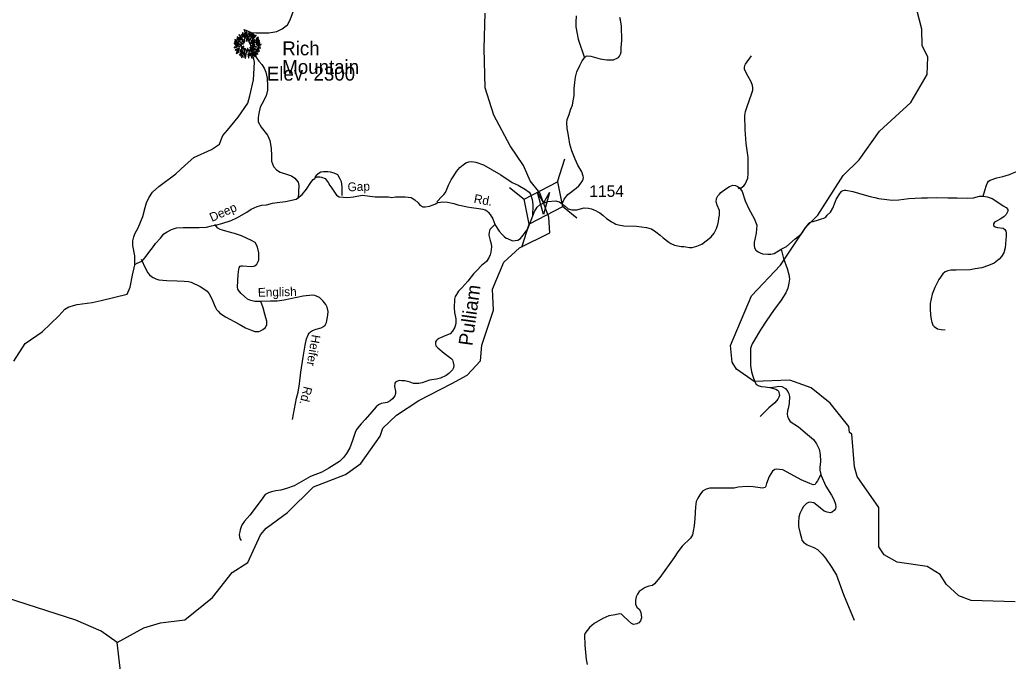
# Model space of a CAD drawing. Extents: x 990631 to 1056237, y 535999 to 585651.
# Drawn here: x 1001806 to 1012421, y 572807 to 579700 of the extents above; entities that cross this region are included whole.
import ezdxf

# ---------------------------------------------------------------- set-up
doc = ezdxf.new("R2010")
doc.units = 0
for name, color, linetype in [('Exist Boundary Political CountyLine', 7, 'Continuous'), ('Exist Geographical Mountain Summit CELL', 7, 'Continuous'), ('Exist Geographical Mountain Summit Elevation Number Label', 7, 'Continuous'), ('Exist Geographical Mountain Summit Label', 7, 'Continuous'), ('Exist Hydrographic Creek Single Shore', 7, 'Continuous'), ('Exist Hydrographic Creek Single Shore Label', 7, 'Continuous'), ('Exist Hydrographic River Shore', 7, 'Continuous'), ('Exist Road Non-System Type 51', 7, 'Continuous'), ('Exist Road Non-System Type 51 Label', 7, 'Continuous'), ('Exist Road Secondary Structure Standard Bridge Attributed CELL', 7, 'Continuous'), ('Exist Road Secondary Structure Standard Bridge CELL', 7, 'Continuous'), ('Exist Road Secondary Type 51 Attributed', 7, 'Continuous'), ('Exist Road Secondary Type 51 Label', 7, 'Continuous'), ('Exist Road Secondary Type 51 Number Label', 7, 'Continuous')]:
    doc.layers.add(name, color=color, linetype=linetype)

msp = doc.modelspace()

# ---------------------------------------------------------------- linework, layer by layer
at = {"layer": 'Exist Boundary Political CountyLine'}
msp.add_lwpolyline([(1001742, 576032), (1001865, 576222), (1002045, 576348), (1002225, 576517), (1002291, 576592), (1002332, 576617), (1002423, 576642), (1002584, 576663), (1002681, 576685), (1002961, 576752), (1002990, 576825), (1003016, 576956), (1003042, 577066), (1003041, 577162), (1003021, 577274), (1003022, 577324), (1003032, 577366), (1003043, 577400), (1003077, 577463), (1003129, 577585), (1003154, 577682), (1003168, 577734), (1003192, 577787), (1003230, 577846), (1003300, 577910), (1003481, 578044), (1003582, 578136), (1003675, 578219), (1003866, 578307), (1003952, 578364), (1003967, 578404), (1003987, 578455), (1004037, 578513), (1004153, 578652), (1004257, 578804), (1004277, 578884), (1004317, 579055), (1004327, 579244), (1004287, 579424), (1004252, 579501), (1004215, 579596), (1004252, 579581), (1004290, 579564), (1004344, 579560), (1004482, 579561), (1004568, 579574), (1004625, 579602), (1004681, 579647), (1004711, 579700), (1004757, 579824)], dxfattribs=at)
at = {"layer": 'Exist Geographical Mountain Summit CELL'}
for points in [[(1004236, 579571), (1004240, 579519), (1004243, 579519), (1004242, 579572)], [(1004264, 579488), (1004279, 579565), (1004273, 579567), (1004261, 579489)], [(1004113, 579464), (1004154, 579455), (1004155, 579458), (1004114, 579469)], [(1004116, 579484), (1004138, 579475), (1004139, 579478), (1004117, 579489)], [(1004138, 579494), (1004163, 579478), (1004166, 579481), (1004140, 579498)], [(1004139, 579513), (1004178, 579483), (1004180, 579485), (1004142, 579518)], [(1004154, 579466), (1004185, 579455), (1004186, 579457), (1004156, 579471)], [(1004159, 579538), (1004195, 579501), (1004198, 579503), (1004163, 579543)], [(1004167, 579510), (1004200, 579481), (1004202, 579484), (1004170, 579516)], [(1004187, 579540), (1004202, 579518), (1004204, 579519), (1004191, 579544)], [(1004191, 579472), (1004216, 579453), (1004218, 579456), (1004193, 579475)], [(1004197, 579561), (1004224, 579494), (1004227, 579496), (1004203, 579564)], [(1004210, 579485), (1004224, 579469), (1004226, 579471), (1004213, 579488)], [(1004231, 579509), (1004234, 579510), (1004225, 579558), (1004220, 579557)], [(1004241, 579497), (1004243, 579468), (1004245, 579469), (1004245, 579498)], [(1004252, 579517), (1004256, 579517), (1004260, 579564), (1004254, 579564)], [(1004267, 579466), (1004270, 579465), (1004319, 579549), (1004313, 579553)], [(1004282, 579524), (1004285, 579522), (1004295, 579549), (1004290, 579551)], [(1004285, 579448), (1004287, 579445), (1004336, 579481), (1004332, 579486)], [(1004288, 579468), (1004291, 579466), (1004346, 579530), (1004342, 579535)], [(1004302, 579445), (1004303, 579443), (1004381, 579472), (1004380, 579476)], [(1004326, 579540), (1004305, 579506), (1004308, 579505), (1004330, 579536)], [(1004346, 579473), (1004374, 579488), (1004371, 579493), (1004345, 579476)], [(1004346, 579496), (1004348, 579493), (1004371, 579510), (1004367, 579513)], [(1004109, 579405), (1004110, 579400), (1004146, 579411), (1004144, 579414)], [(1004110, 579443), (1004182, 579436), (1004183, 579439), (1004110, 579448)], [(1004119, 579378), (1004121, 579373), (1004167, 579393), (1004165, 579398)], [(1004122, 579426), (1004152, 579427), (1004152, 579431), (1004121, 579431)], [(1004130, 579341), (1004133, 579337), (1004161, 579358), (1004159, 579361)], [(1004136, 579362), (1004165, 579379), (1004163, 579382), (1004134, 579367)], [(1004155, 579417), (1004156, 579412), (1004189, 579420), (1004188, 579424)], [(1004161, 579321), (1004164, 579319), (1004204, 579367), (1004202, 579369)], [(1004172, 579371), (1004175, 579368), (1004210, 579396), (1004208, 579399)], [(1004176, 579353), (1004195, 579371), (1004192, 579373), (1004172, 579356)], [(1004201, 579353), (1004176, 579314), (1004179, 579311), (1004205, 579351)], [(1004182, 579403), (1004184, 579398), (1004213, 579413), (1004212, 579416)], [(1004191, 579442), (1004208, 579440), (1004208, 579442), (1004192, 579446)], [(1004204, 579331), (1004208, 579330), (1004235, 579388), (1004232, 579389)], [(1004211, 579381), (1004214, 579378), (1004224, 579394), (1004223, 579396)], [(1004225, 579286), (1004230, 579285), (1004243, 579374), (1004240, 579375)], [(1004251, 579390), (1004255, 579353), (1004259, 579353), (1004254, 579391)], [(1004267, 579381), (1004276, 579351), (1004280, 579353), (1004269, 579382)], [(1004275, 579401), (1004314, 579366), (1004316, 579371), (1004277, 579404)], [(1004281, 579379), (1004332, 579304), (1004336, 579307), (1004284, 579380)], [(1004286, 579419), (1004347, 579407), (1004348, 579411), (1004288, 579422)], [(1004300, 579399), (1004378, 579361), (1004380, 579366), (1004302, 579402)], [(1004301, 579432), (1004301, 579429), (1004331, 579429), (1004332, 579434)], [(1004314, 579353), (1004344, 579324), (1004347, 579327), (1004316, 579356)], [(1004331, 579354), (1004361, 579328), (1004364, 579332), (1004332, 579356)], [(1004340, 579365), (1004365, 579352), (1004367, 579355), (1004342, 579369)], [(1004344, 579431), (1004397, 579434), (1004397, 579439), (1004345, 579434)], [(1004348, 579445), (1004385, 579452), (1004383, 579457), (1004347, 579447)], [(1004354, 579389), (1004375, 579381), (1004377, 579385), (1004355, 579392)], [(1004359, 579419), (1004386, 579417), (1004386, 579421), (1004360, 579422)], [(1004363, 579402), (1004392, 579395), (1004392, 579400), (1004364, 579407)], [(1004186, 579294), (1004191, 579291), (1004202, 579316), (1004198, 579318)], [(1004216, 579296), (1004228, 579339), (1004224, 579339), (1004211, 579297)], [(1004257, 579331), (1004261, 579289), (1004265, 579290), (1004261, 579331)], [(1004277, 579315), (1004271, 579344), (1004268, 579344), (1004272, 579314)], [(1004281, 579336), (1004299, 579286), (1004303, 579288), (1004284, 579337)], [(1004292, 579342), (1004308, 579312), (1004312, 579315), (1004296, 579343)]]:
    msp.add_lwpolyline(points, close=True, dxfattribs=at)
at = {"layer": 'Exist Hydrographic Creek Single Shore'}
for points in [[(1012497, 573446), (1012023, 573459), (1011891, 573508), (1011753, 573635), (1011690, 573738), (1011551, 573826), (1011228, 573872), (1011088, 573950), (1011033, 574037), (1011030, 574460), (1010800, 574793), (1010770, 574896), (1010740, 575247), (1010715, 575264), (1010709, 575330), (1010509, 575580), (1010306, 575745), (1010075, 575828), (1009691, 575813), (1009504, 575945), (1009456, 576021), (1009437, 576199), (1009664, 576733), (1009975, 577064), (1010247, 577472), (1010376, 577601), (1010649, 578026), (1010821, 578196), (1011040, 578503), (1011376, 578812), (1011552, 579113), (1011559, 579297), (1011496, 579423), (1011494, 579600), (1011390, 580003)], [(1002852, 573007), (1003140, 573165), (1003317, 573218), (1003577, 573252), (1003877, 573492), (1004086, 573760), (1004256, 573868), (1004391, 574164), (1004452, 574238), (1004683, 574404), (1004959, 574681), (1005305, 574812), (1005467, 574930), (1005677, 575225), (1005705, 575313), (1005852, 575451), (1006091, 575610), (1006447, 575790), (1006611, 575882), (1006754, 576035), (1006769, 576203), (1006892, 576578), (1006882, 576805), (1007005, 577096), (1007173, 577249), (1007498, 577411), (1007486, 577580), (1007392, 577839), (1007286, 577969), (1007215, 578133), (1007074, 578345), (1006898, 578675), (1006804, 578969), (1006792, 579393), (1006804, 579770)]]:
    msp.add_lwpolyline(points, dxfattribs=at)
at = {"layer": 'Exist Hydrographic River Shore'}
for points in [[(1002852, 573007), (1002680, 573129), (1002409, 573249), (1001559, 573519), (1001362, 573656)], [(1004246, 570577), (1003938, 570836), (1003298, 571633), (1003158, 571678), (1002773, 571650), (1002617, 571722), (1002532, 571911), (1002546, 572091), (1002672, 572364), (1002829, 572584), (1002884, 572731), (1002852, 573007)]]:
    msp.add_lwpolyline(points, dxfattribs=at)
at = {"layer": 'Exist Road Non-System Type 51'}
for points in [[(1007782, 579741), (1007778, 579673), (1007778, 579625), (1007802, 579490), (1007869, 579292)], [(1007869, 579292), (1007888, 579309), (1007900, 579311), (1007940, 579308), (1007989, 579294), (1008039, 579280), (1008065, 579276), (1008087, 579273), (1008109, 579270), (1008155, 579269), (1008181, 579270), (1008197, 579275), (1008215, 579283), (1008234, 579294), (1008248, 579310), (1008259, 579331), (1008264, 579357), (1008265, 579399), (1008270, 579477), (1008267, 579635), (1008262, 579675), (1008259, 579699), (1008250, 579726)], [(1004300, 579563), (1004314, 579435), (1004321, 579367), (1004349, 579292), (1004374, 579255), (1004407, 579218), (1004431, 579181), (1004448, 579138), (1004462, 579072), (1004467, 578989), (1004467, 578943), (1004451, 578884), (1004406, 578795), (1004387, 578762), (1004373, 578694), (1004365, 578649), (1004368, 578605), (1004400, 578545), (1004465, 578461), (1004482, 578429), (1004491, 578402), (1004500, 578364), (1004506, 578318), (1004508, 578240), (1004510, 578181), (1004532, 578125), (1004563, 578086), (1004604, 578064), (1004683, 578036), (1004725, 578022), (1004760, 577997), (1004775, 577981), (1004795, 577954), (1004803, 577920), (1004795, 577778)], [(1007631, 577723), (1007654, 577774), (1007692, 577821), (1007782, 577890), (1007811, 577915), (1007836, 577948), (1007849, 577968), (1007858, 577988), (1007860, 578004), (1007855, 578020), (1007842, 578066), (1007799, 578136), (1007769, 578201), (1007734, 578292), (1007714, 578363), (1007703, 578435), (1007691, 578496), (1007686, 578532), (1007680, 578594), (1007685, 578628), (1007705, 578681), (1007722, 578733), (1007740, 578784), (1007747, 578806), (1007752, 578846), (1007760, 578887), (1007760, 578961), (1007766, 579025), (1007774, 579085), (1007790, 579139), (1007820, 579208), (1007844, 579259), (1007869, 579292)], [(1009529, 577884), (1009529, 577886), (1009554, 577895), (1009580, 577916), (1009595, 577934), (1009612, 577967), (1009623, 577999), (1009627, 578049), (1009629, 578219), (1009608, 578369), (1009597, 578520), (1009594, 578672), (1009599, 578714), (1009617, 578767), (1009665, 578902), (1009677, 578945), (1009678, 578969), (1009676, 578995), (1009662, 579032), (1009628, 579091), (1009599, 579144), (1009590, 579168), (1009589, 579187), (1009591, 579209), (1009600, 579224), (1009665, 579312)], [(1006286, 577742), (1006343, 577804), (1006361, 577823), (1006378, 577845), (1006397, 577888), (1006409, 577924), (1006438, 577981), (1006466, 578024), (1006497, 578069), (1006533, 578112), (1006568, 578143), (1006597, 578162), (1006627, 578175), (1006659, 578178), (1006705, 578170), (1006786, 578141), (1006973, 578033), (1007094, 577951), (1007159, 577921), (1007236, 577876), (1007277, 577849), (1007289, 577827), (1007308, 577767), (1007316, 577716), (1007311, 577585)], [(1012152, 577806), (1012168, 577864), (1012186, 577923), (1012197, 577949), (1012208, 577964), (1012226, 577976), (1012299, 578003), (1012364, 578017), (1012434, 578039), (1012467, 578050), (1012503, 578067), (1012538, 578087), (1012557, 578113), (1012576, 578150)], [(1005270, 577810), (1005267, 577904), (1005261, 577958), (1005242, 577993), (1005220, 578034), (1005184, 578051), (1005144, 578062), (1005113, 578067), (1005067, 578065), (1005040, 578062), (1005020, 578050), (1004989, 578025), (1004976, 578004)], [(1009982, 577236), (1009984, 577236), (1010039, 577264), (1010132, 577347), (1010196, 577397), (1010212, 577415), (1010229, 577442), (1010254, 577479), (1010269, 577497), (1010282, 577514), (1010292, 577522), (1010306, 577527), (1010326, 577533), (1010383, 577549), (1010417, 577560), (1010441, 577569), (1010462, 577580), (1010478, 577600), (1010512, 577633), (1010537, 577674), (1010561, 577741), (1010572, 577769), (1010614, 577835), (1010635, 577859), (1010649, 577866), (1010664, 577870), (1010678, 577869), (1010753, 577855), (1010874, 577819), (1010938, 577801), (1010989, 577789), (1011027, 577778), (1011119, 577767), (1011174, 577763), (1011247, 577766), (1011355, 577781), (1011491, 577786), (1011555, 577786), (1011654, 577791), (1011772, 577785), (1011872, 577785), (1011982, 577784), (1012048, 577788), (1012112, 577803), (1012152, 577806)], [(1012152, 577806), (1012196, 577797), (1012250, 577779), (1012310, 577739), (1012367, 577701), (1012398, 577682), (1012418, 577661), (1012417, 577643), (1012400, 577608), (1012375, 577583), (1012336, 577558), (1012295, 577535), (1012275, 577524), (1012262, 577506), (1012264, 577496), (1012268, 577486), (1012282, 577476), (1012307, 577467), (1012365, 577459), (1012383, 577448), (1012394, 577430), (1012399, 577410), (1012400, 577378), (1012388, 577250), (1012372, 577196), (1012347, 577155), (1012322, 577128), (1012269, 577086), (1012210, 577058), (1012139, 577034), (1012066, 577022), (1012012, 577014), (1011862, 577011), (1011806, 577009), (1011771, 577002), (1011745, 576991), (1011718, 576970), (1011676, 576909), (1011633, 576823), (1011605, 576750), (1011584, 576652), (1011584, 576590), (1011586, 576528), (1011594, 576478), (1011599, 576450), (1011612, 576419), (1011625, 576403), (1011661, 576380), (1011700, 576370), (1011742, 576367)], [(1004396, 576674), (1004330, 576674), (1004286, 576682), (1004252, 576699), (1004219, 576726), (1004182, 576757), (1004163, 576784), (1004148, 576805), (1004143, 576827), (1004151, 576961), (1004159, 577020), (1004164, 577036), (1004174, 577052), (1004184, 577056), (1004198, 577057), (1004296, 577050), (1004316, 577051), (1004332, 577057), (1004351, 577074), (1004366, 577101), (1004372, 577119), (1004375, 577197), (1004359, 577258), (1004348, 577282), (1004333, 577307), (1004295, 577328), (1004187, 577378), (1004112, 577404), (1004044, 577422), (1003985, 577438), (1003957, 577447), (1003934, 577460), (1003916, 577481), (1003901, 577499)], [(1006909, 577501), (1006870, 577462), (1006855, 577445), (1006851, 577433), (1006846, 577419), (1006843, 577387), (1006859, 577328), (1006868, 577292), (1006871, 577260), (1006865, 577202), (1006858, 577174), (1006843, 577143), (1006820, 577104), (1006766, 577061), (1006716, 577007), (1006677, 576970), (1006618, 576892), (1006552, 576820), (1006519, 576785), (1006497, 576748), (1006483, 576727), (1006476, 576699), (1006471, 576603), (1006475, 576553), (1006489, 576486), (1006489, 576438), (1006478, 576396), (1006454, 576353), (1006427, 576326), (1006383, 576306), (1006326, 576283), (1006306, 576276), (1006289, 576261), (1006277, 576249), (1006272, 576239), (1006270, 576219), (1006275, 576197), (1006294, 576174), (1006364, 576118), (1006435, 576064), (1006452, 576045), (1006461, 576017), (1006466, 575985), (1006465, 575961), (1006452, 575937), (1006413, 575900), (1006384, 575877), (1006325, 575849), (1006281, 575839), (1006205, 575827), (1006128, 575800), (1006091, 575791), (1006035, 575793), (1005998, 575804), (1005940, 575820), (1005908, 575821), (1005884, 575822), (1005864, 575817), (1005842, 575805), (1005833, 575794), (1005832, 575758), (1005842, 575709), (1005842, 575683), (1005833, 575658), (1005810, 575628), (1005783, 575605), (1005750, 575588), (1005686, 575576), (1005659, 575561), (1005635, 575540), (1005587, 575486), (1005514, 575406), (1005472, 575359), (1005450, 575332), (1005425, 575301), (1005412, 575275), (1005396, 575234), (1005380, 575178), (1005352, 575099), (1005314, 575038), (1005282, 574995), (1005239, 574953), (1005126, 574883), (1005049, 574839), (1004927, 574791), (1004827, 574734), (1004752, 574691), (1004669, 574662), (1004608, 574646), (1004556, 574639), (1004510, 574629), (1004477, 574618), (1004440, 574599), (1004398, 574539), (1004275, 574375), (1004221, 574312), (1004196, 574277), (1004183, 574250), (1004174, 574218), (1004169, 574196)], [(1009982, 577236), (1010009, 577135), (1010047, 577026), (1010065, 576963), (1010071, 576913), (1010066, 576871), (1010054, 576816), (1010034, 576766), (1009982, 576688), (1009900, 576576), (1009829, 576473), (1009761, 576367), (1009691, 576253), (1009670, 576216), (1009661, 576190), (1009654, 576168), (1009653, 576126), (1009652, 576040), (1009654, 575986), (1009664, 575918), (1009678, 575869), (1009700, 575808), (1009715, 575786), (1009735, 575769), (1009769, 575760), (1009812, 575755), (1009862, 575747), (1009864, 575747)], [(1003110, 577129), (1003157, 577026), (1003183, 576979), (1003200, 576958), (1003220, 576942), (1003239, 576931), (1003269, 576918), (1003301, 576907), (1003384, 576898), (1003498, 576894), (1003570, 576890), (1003618, 576886), (1003648, 576879), (1003745, 576834), (1003794, 576802), (1003819, 576782), (1003840, 576755), (1003868, 576702), (1003892, 576641), (1003907, 576609), (1003920, 576588), (1003938, 576569), (1003953, 576549), (1004014, 576507), (1004163, 576430), (1004232, 576388), (1004303, 576361), (1004329, 576352), (1004353, 576349), (1004375, 576351), (1004391, 576358), (1004417, 576371), (1004444, 576394), (1004459, 576424), (1004459, 576460), (1004448, 576498), (1004439, 576535), (1004419, 576603), (1004396, 576674)], [(1004734, 575406), (1004779, 575635), (1004795, 575700), (1004810, 575788), (1004825, 575913), (1004850, 576075), (1004872, 576204), (1004887, 576273), (1004902, 576315), (1004915, 576333), (1004927, 576346), (1004948, 576361), (1004990, 576374), (1005043, 576388), (1005069, 576403), (1005086, 576417), (1005101, 576446), (1005115, 576524), (1005117, 576564), (1005106, 576610), (1005093, 576639), (1005066, 576678), (1005025, 576717), (1004976, 576737), (1004950, 576742), (1004848, 576729), (1004646, 576686), (1004572, 576678), (1004500, 576677), (1004396, 576674)], [(1009864, 575747), (1009902, 575736), (1009926, 575731), (1009943, 575720), (1009955, 575708), (1009962, 575682), (1009963, 575662), (1009959, 575646), (1009946, 575622), (1009915, 575585), (1009849, 575529), (1009758, 575438)], [(1009864, 575747), (1009923, 575757), (1009957, 575764), (1009991, 575759), (1010028, 575739), (1010053, 575707), (1010064, 575680), (1010073, 575650), (1010069, 575578), (1010057, 575524), (1010052, 575499), (1010047, 575461), (1010050, 575439), (1010063, 575410), (1010078, 575382), (1010167, 575325), (1010264, 575243), (1010328, 575191), (1010362, 575142), (1010389, 575085), (1010403, 575027), (1010406, 574952), (1010398, 574887), (1010397, 574859), (1010407, 574812)], [(1010407, 574812), (1010371, 574747), (1010357, 574726), (1010346, 574706), (1010326, 574701), (1010292, 574718), (1010197, 574755), (1010046, 574838), (1009999, 574864), (1009963, 574869), (1009935, 574872), (1009913, 574867), (1009890, 574850), (1009852, 574791), (1009824, 574716), (1009817, 574688), (1009809, 574674), (1009782, 574667), (1009683, 574680), (1009619, 574685), (1009521, 574678), (1009478, 574667), (1009310, 574665), (1009218, 574666), (1009178, 574657), (1009137, 574636), (1009108, 574595), (1009086, 574560), (1009071, 574523), (1009063, 574465), (1009057, 574339), (1009048, 574263), (1009036, 574206), (1009029, 574166), (1009008, 574128), (1008921, 574043), (1008873, 573981), (1008835, 573920), (1008680, 573707), (1008623, 573637), (1008601, 573620), (1008560, 573615), (1008522, 573600), (1008458, 573556), (1008439, 573529), (1008424, 573500), (1008417, 573464), (1008420, 573420), (1008433, 573389), (1008456, 573366), (1008477, 573334), (1008483, 573273), (1008472, 573240), (1008455, 573218), (1008431, 573207), (1008398, 573202), (1008377, 573211), (1008342, 573240), (1008286, 573296), (1008268, 573311), (1008248, 573317), (1008200, 573305), (1008131, 573293), (1008068, 573265), (1007973, 573214), (1007923, 573168), (1007873, 573106), (1007870, 573088), (1007873, 572980), (1007888, 572827), (1007898, 572771)], [(1010407, 574812), (1010407, 574810), (1010461, 574688), (1010522, 574592), (1010545, 574551), (1010560, 574517), (1010567, 574493), (1010570, 574465), (1010567, 574445), (1010557, 574429), (1010532, 574408), (1010508, 574403), (1010478, 574408), (1010444, 574421), (1010365, 574485), (1010335, 574508), (1010311, 574513), (1010285, 574516), (1010255, 574501), (1010222, 574468), (1010205, 574439), (1010183, 574393), (1010172, 574356), (1010168, 574296), (1010169, 574256), (1010188, 574179), (1010201, 574131), (1010206, 574109), (1010221, 574086), (1010260, 574059), (1010333, 574030), (1010371, 574007), (1010423, 573957), (1010460, 573916), (1010528, 573814), (1010578, 573730), (1010651, 573525), (1010768, 573249)], [(1004169, 574196), (1004164, 574170), (1004167, 574142), (1004169, 574126), (1004182, 574104)]]:
    msp.add_lwpolyline(points, dxfattribs=at)
at = {"layer": 'Exist Road Secondary Structure Standard Bridge Attributed CELL'}
msp.add_lwpolyline([(1007493, 577843), (1007430, 577608), (1007367, 577843), (1007430, 577730)], close=True, dxfattribs=at)
at = {"layer": 'Exist Road Secondary Structure Standard Bridge CELL'}
for p, q in [((1007580, 577958), (1007659, 578204)), ((1007067, 577898), (1007221, 577773)), ((1007634, 577696), (1007787, 577570)), ((1007197, 577258), (1007275, 577504))]:
    msp.add_line(p, q, dxfattribs=at)
msp.add_lwpolyline([(1007221, 577773), (1007580, 577959), (1007635, 577691), (1007275, 577504)], close=True, dxfattribs=at)
at = {"layer": 'Exist Road Secondary Type 51 Attributed'}
for points in [[(1003042, 577069), (1003067, 577084), (1003118, 577107), (1003131, 577120), (1003152, 577144), (1003180, 577185), (1003219, 577231), (1003233, 577250), (1003263, 577295), (1003316, 577354), (1003353, 577399), (1003388, 577422), (1003435, 577448), (1003488, 577463), (1003562, 577469), (1003659, 577467), (1003731, 577467), (1003812, 577471), (1003864, 577486), (1003923, 577497), (1003975, 577512), (1004075, 577544), (1004136, 577570), (1004244, 577634), (1004291, 577665), (1004354, 577694), (1004406, 577708), (1004455, 577713), (1004519, 577729), (1004569, 577737), (1004660, 577749), (1004773, 577773), (1004838, 577823), (1004887, 577881), (1004933, 577951), (1004958, 577982), (1004973, 577995), (1004980, 578001), (1004984, 578005), (1005004, 578013), (1005028, 578012), (1005047, 578007), (1005084, 577993), (1005118, 577952), (1005136, 577918), (1005157, 577892), (1005208, 577815), (1005236, 577799), (1005328, 577789), (1005391, 577799), (1005484, 577814), (1005623, 577796), (1005765, 577797), (1005803, 577792), (1005841, 577796), (1005896, 577799), (1005945, 577798), (1006010, 577790), (1006048, 577766), (1006085, 577733), (1006104, 577709), (1006133, 577689), (1006160, 577690), (1006205, 577697), (1006244, 577712), (1006272, 577722), (1006287, 577732), (1006299, 577735), (1006349, 577744), (1006398, 577740), (1006466, 577724), (1006512, 577712), (1006565, 577699), (1006609, 577689), (1006657, 577683), (1006737, 577673), (1006778, 577665), (1006804, 577659), (1006822, 577648), (1006837, 577633), (1006858, 577609), (1006887, 577562), (1006907, 577505), (1006909, 577501), (1006956, 577427), (1006985, 577394), (1007007, 577370), (1007028, 577355), (1007042, 577350), (1007098, 577324), (1007153, 577332), (1007183, 577350), (1007212, 577386), (1007234, 577413), (1007262, 577455), (1007333, 577641), (1007363, 577687), (1007394, 577716), (1007474, 577747), (1007563, 577753), (1007586, 577747)], [(1008067, 577599), (1008108, 577566), (1008136, 577548), (1008162, 577530), (1008189, 577514), (1008206, 577504), (1008234, 577495), (1008292, 577484), (1008428, 577481), (1008481, 577475), (1008537, 577467), (1008562, 577462), (1008591, 577454), (1008638, 577423), (1008684, 577386), (1008716, 577358), (1008778, 577311), (1008799, 577295), (1008837, 577279), (1008873, 577271), (1008909, 577263), (1008938, 577263), (1008959, 577260), (1008999, 577254), (1009028, 577254), (1009076, 577267), (1009131, 577290), (1009190, 577334), (1009231, 577368), (1009263, 577407), (1009289, 577456), (1009302, 577500), (1009308, 577532), (1009313, 577563), (1009320, 577600), (1009322, 577652), (1009297, 577707), (1009283, 577742), (1009287, 577778), (1009303, 577809), (1009320, 577827), (1009336, 577845), (1009387, 577885), (1009428, 577907), (1009462, 577921), (1009491, 577919), (1009509, 577912), (1009535, 577895)], [(1009535, 577895), (1009564, 577853), (1009595, 577753), (1009636, 577668), (1009693, 577564), (1009720, 577493), (1009715, 577406), (1009692, 577306), (1009693, 577276), (1009696, 577248), (1009712, 577226), (1009734, 577207), (1009757, 577194), (1009782, 577186), (1009838, 577183), (1009870, 577183), (1009907, 577188), (1009982, 577236)], [(1007586, 577747), (1007603, 577743), (1007664, 577698), (1007697, 577667), (1007735, 577658), (1007787, 577656), (1007867, 577678), (1007915, 577674), (1007946, 577667), (1007970, 577658), (1007990, 577650), (1008013, 577637), (1008034, 577625), (1008067, 577599)]]:
    msp.add_lwpolyline(points, dxfattribs=at)

# ---------------------------------------------------------------- texts
at = {"layer": 'Exist Geographical Mountain Summit Elevation Number Label'}
msp.add_text('Elev. 2300', height=150, dxfattribs=at).set_placement((1004459, 579046))
at = {"layer": 'Exist Geographical Mountain Summit Label'}
for s, p in [('Rich', (1004625, 579318)), ('Mountain', (1004625, 579119))]:
    msp.add_text(s, height=150, dxfattribs=at).set_placement(p)
at = {"layer": 'Exist Hydrographic Creek Single Shore Label'}
msp.add_text('Pulliam', height=150, rotation=82.0676, dxfattribs=at).set_placement((1006665, 576190))
at = {"layer": 'Exist Road Non-System Type 51 Label'}
for s, rotation, p in [('English', 1.3895, (1004364, 576723)), ('Heifer', 260.2603, (1004943, 576322)), ('Rd.', 256.1711, (1004857, 575767))]:
    msp.add_text(s, height=95, rotation=rotation, dxfattribs=at).set_placement(p)
at = {"layer": 'Exist Road Secondary Type 51 Label'}
for s, rotation, p in [('Gap', 2.169, (1005328, 577856)), ('Rd.', 349.8715, (1006677, 577734)), ('Deep ', 24.142, (1003870, 577527))]:
    msp.add_text(s, height=95, rotation=rotation, dxfattribs=at).set_placement(p)
at = {"layer": 'Exist Road Secondary Type 51 Number Label'}
msp.add_text('1154', height=125, dxfattribs=at).set_placement((1007922, 577797))

doc.saveas('drawing.dxf')
